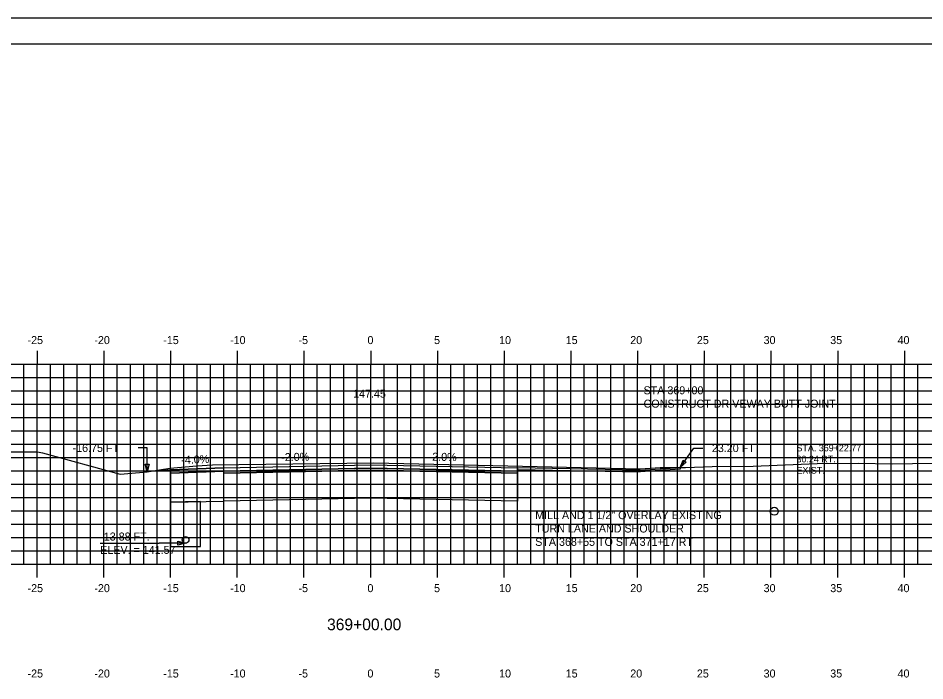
# Model space of a CAD drawing. Extents: x 1147855 to 1148025, y 608981 to 609091.
# Drawn here: x 1147911.8 to 1147979.7, y 609041.6 to 609091.3 of the extents above; entities that cross this region are included whole.
import ezdxf

# ---------------------------------------------------------------- set-up
doc = ezdxf.new("R2010")
doc.units = 0
for name, color, linetype in [('ANNOTATION', 7, 'Continuous'), ('BORDER', 7, 'Continuous'), ('D_Drainage_Underdrain', 7, 'Continuous'), ('D_Drainage_Underdrain_06in', 7, 'Continuous'), ('D_Roadway_Centerline', 7, 'Continuous'), ('D_Roadway_Centerline_Text', 7, 'Continuous'), ('D_Roadway_Drive_Paved', 7, 'Continuous'), ('D_Roadway_Edge_Shoulder', 7, 'Continuous'), ('D_Roadway_Edge_TW', 7, 'Continuous'), ('D_Roadway_Pavement', 7, 'Continuous'), ('D_Roadway_SlopeLines', 7, 'Continuous'), ('D_Roadway_SubGrade', 7, 'Continuous'), ('D_Text_Monospaced', 7, 'Continuous'), ('D_Text_Standard', 7, 'Continuous'), ('H_V ANNOTATION', 7, 'Continuous'), ('MAJOR', 7, 'Continuous'), ('MINOR', 7, 'Continuous'), ('PLOT BOUNDARY', 7, 'Continuous'), ('S_Drainage_Invert', 7, 'Continuous'), ('S_Roadway_Centerline', 7, 'Continuous')]:
    doc.layers.add(name, color=color, linetype=linetype)

msp = doc.modelspace()

# ---------------------------------------------------------------- linework, layer by layer
msp.add_lwpolyline([(1147923.21, 609057.406), (1147923.211, 609057.406), (1147927.211, 609057.566), (1147938.211, 609057.786), (1147949.211, 609057.566)])
at = {"layer": 'BORDER'}
msp.add_lwpolyline([(1147863.211, 608984.335), (1148023.211, 608984.335), (1148023.211, 609089.335), (1147863.211, 609089.335)], close=True, dxfattribs=at)
at = {"layer": 'D_Drainage_Underdrain'}
msp.add_lwpolyline([(1147923.211, 609054.986), (1147923.211, 609051.656), (1147925.461, 609051.656), (1147925.461, 609055.031)], close=True, dxfattribs=at)
at = {"layer": 'D_Drainage_Underdrain_06in'}
msp.add_lwpolyline([(1147924.336, 609052.406), (1147924.413, 609052.394), (1147924.482, 609052.359), (1147924.538, 609052.303), (1147924.573, 609052.234), (1147924.586, 609052.156), (1147924.573, 609052.079), (1147924.538, 609052.009), (1147924.482, 609051.954), (1147924.413, 609051.918), (1147924.336, 609051.906), (1147924.258, 609051.918), (1147924.189, 609051.954), (1147924.133, 609052.009), (1147924.098, 609052.079), (1147924.086, 609052.156), (1147924.098, 609052.234), (1147924.133, 609052.303), (1147924.189, 609052.359), (1147924.258, 609052.394)], close=True, dxfattribs=at)
at = {"layer": 'D_Roadway_Drive_Paved'}
msp.add_line((1147958.411, 609057.382), (1147961.411, 609057.573), dxfattribs=at)
msp.add_lwpolyline([(1147961.411, 609057.573), (1147961.411, 609057.448), (1147958.411, 609057.257)], dxfattribs=at)
at = {"layer": 'D_Roadway_Edge_Shoulder'}
msp.add_line((1147949.211, 609057.441), (1147958.411, 609057.257), dxfattribs=at)
msp.add_lwpolyline([(1147927.211, 609057.566), (1147923.211, 609057.406), (1147923.211, 609057.156), (1147927.211, 609057.316)], close=True, dxfattribs=at)
msp.add_lwpolyline([(1147958.411, 609057.257), (1147958.411, 609057.382), (1147949.211, 609057.566)], dxfattribs=at)
at = {"layer": 'D_Roadway_Edge_TW'}
msp.add_lwpolyline([(1147927.211, 609057.316), (1147927.211, 609057.566), (1147938.211, 609057.786), (1147949.211, 609057.566), (1147949.211, 609057.316), (1147938.211, 609057.536)], close=True, dxfattribs=at)
at = {"layer": 'D_Roadway_Pavement'}
msp.add_lwpolyline([(1147927.211, 609057.15), (1147927.211, 609057.316), (1147938.211, 609057.536), (1147949.211, 609057.316), (1147949.211, 609057.15), (1147938.211, 609057.37)], close=True, dxfattribs=at)
at = {"layer": 'D_Roadway_SlopeLines'}
msp.add_line((1147923.211, 609057.406), (1147921.464, 609057.25), dxfattribs=at)
at = {"layer": 'D_Roadway_SubGrade'}
for points in [[(1147923.21, 609054.986), (1147927.211, 609055.066), (1147927.211, 609057.15), (1147927.211, 609057.316), (1147923.211, 609057.156), (1147923.211, 609057.406), (1147923.21, 609057.406)], [(1147927.211, 609055.066), (1147927.211, 609057.15), (1147938.211, 609057.37), (1147949.211, 609057.15), (1147949.211, 609055.066), (1147938.211, 609055.286)]]:
    msp.add_lwpolyline(points, close=True, dxfattribs=at)
at = {"layer": 'D_Text_Standard'}
msp.add_line((1147917.943, 609051.906), (1147922.357, 609051.906), dxfattribs=at)
for points in [[(1147921.464, 609057.25), (1147921.473, 609059.045), (1147920.793, 609059.045)], [(1147961.411, 609057.573), (1147962.422, 609059.039), (1147963.102, 609059.039)], [(1147924.336, 609051.906), (1147923.037, 609051.906), (1147922.357, 609051.906)]]:
    msp.add_lwpolyline(points, dxfattribs=at)
for points in [[(1147921.464, 609057.25), (1147921.321, 609057.832), (1147921.612, 609057.831)], [(1147961.411, 609057.573), (1147961.621, 609058.135), (1147961.861, 609057.97)], [(1147924.336, 609051.906), (1147923.753, 609051.761), (1147923.753, 609052.052)]]:
    msp.add_lwpolyline(points, close=True, dxfattribs=at)
at = {"layer": 'MAJOR'}
for p, q in [((1147913.211, 609066.337), (1147913.211, 609065.335)), ((1147918.211, 609066.337), (1147918.211, 609065.335)), ((1147923.211, 609066.337), (1147923.211, 609065.335)), ((1147928.211, 609066.337), (1147928.211, 609065.335)), ((1147933.211, 609066.337), (1147933.211, 609065.335)), ((1147938.211, 609066.337), (1147938.211, 609065.335)), ((1147943.211, 609066.337), (1147943.211, 609065.335)), ((1147948.211, 609066.337), (1147948.211, 609065.335)), ((1147953.211, 609066.337), (1147953.211, 609065.335)), ((1147958.211, 609066.337), (1147958.211, 609065.335)), ((1147963.211, 609066.337), (1147963.211, 609065.335)), ((1147968.211, 609066.337), (1147968.211, 609065.335)), ((1147973.211, 609066.337), (1147973.211, 609065.335)), ((1147978.211, 609066.337), (1147978.211, 609065.335)), ((1147868.211, 609065.335), (1148008.211, 609065.335)), ((1147868.211, 609065.335), (1148008.211, 609065.335)), ((1147913.211, 609050.335), (1147913.211, 609065.335)), ((1147918.211, 609050.335), (1147918.211, 609065.335)), ((1147923.211, 609050.335), (1147923.211, 609065.335)), ((1147928.211, 609050.335), (1147928.211, 609065.335)), ((1147933.211, 609050.335), (1147933.211, 609065.335)), ((1147938.211, 609050.335), (1147938.211, 609065.335)), ((1147943.211, 609050.335), (1147943.211, 609065.335)), ((1147948.211, 609050.335), (1147948.211, 609065.335)), ((1147953.211, 609050.335), (1147953.211, 609065.335)), ((1147958.211, 609050.335), (1147958.211, 609065.335)), ((1147963.211, 609050.335), (1147963.211, 609065.335)), ((1147968.211, 609050.335), (1147968.211, 609065.335)), ((1147973.211, 609050.335), (1147973.211, 609065.335)), ((1147978.211, 609050.335), (1147978.211, 609065.335)), ((1147868.211, 609060.335), (1148008.211, 609060.335)), ((1147868.211, 609055.335), (1148008.211, 609055.335)), ((1147868.211, 609050.335), (1148008.211, 609050.335)), ((1147868.211, 609050.335), (1148008.211, 609050.335)), ((1147913.211, 609049.333), (1147913.211, 609050.335)), ((1147918.211, 609049.333), (1147918.211, 609050.335)), ((1147923.211, 609049.333), (1147923.211, 609050.335)), ((1147928.211, 609049.333), (1147928.211, 609050.335)), ((1147933.211, 609049.333), (1147933.211, 609050.335)), ((1147938.211, 609049.333), (1147938.211, 609050.335)), ((1147943.211, 609049.333), (1147943.211, 609050.335)), ((1147948.211, 609049.333), (1147948.211, 609050.335)), ((1147953.211, 609049.333), (1147953.211, 609050.335)), ((1147958.211, 609049.333), (1147958.211, 609050.335)), ((1147963.211, 609049.333), (1147963.211, 609050.335)), ((1147968.211, 609049.333), (1147968.211, 609050.335)), ((1147973.211, 609049.333), (1147973.211, 609050.335)), ((1147978.211, 609049.333), (1147978.211, 609050.335))]:
    msp.add_line(p, q, dxfattribs=at)
at = {"layer": 'MINOR'}
for p, q in [((1147912.211, 609050.335), (1147912.211, 609065.335)), ((1147914.211, 609050.335), (1147914.211, 609065.335)), ((1147915.211, 609050.335), (1147915.211, 609065.335)), ((1147916.211, 609050.335), (1147916.211, 609065.335)), ((1147917.211, 609050.335), (1147917.211, 609065.335)), ((1147919.211, 609050.335), (1147919.211, 609065.335)), ((1147920.211, 609050.335), (1147920.211, 609065.335)), ((1147921.211, 609050.335), (1147921.211, 609065.335)), ((1147922.211, 609050.335), (1147922.211, 609065.335)), ((1147924.211, 609050.335), (1147924.211, 609065.335)), ((1147925.211, 609050.335), (1147925.211, 609065.335)), ((1147926.211, 609050.335), (1147926.211, 609065.335)), ((1147927.211, 609050.335), (1147927.211, 609065.335)), ((1147929.211, 609050.335), (1147929.211, 609065.335)), ((1147930.211, 609050.335), (1147930.211, 609065.335)), ((1147931.211, 609050.335), (1147931.211, 609065.335)), ((1147932.211, 609050.335), (1147932.211, 609065.335)), ((1147934.211, 609050.335), (1147934.211, 609065.335)), ((1147935.211, 609050.335), (1147935.211, 609065.335)), ((1147936.211, 609050.335), (1147936.211, 609065.335)), ((1147937.211, 609050.335), (1147937.211, 609065.335)), ((1147939.211, 609050.335), (1147939.211, 609065.335)), ((1147940.211, 609050.335), (1147940.211, 609065.335)), ((1147941.211, 609050.335), (1147941.211, 609065.335)), ((1147942.211, 609050.335), (1147942.211, 609065.335)), ((1147944.211, 609050.335), (1147944.211, 609065.335)), ((1147945.211, 609050.335), (1147945.211, 609065.335)), ((1147946.211, 609050.335), (1147946.211, 609065.335)), ((1147947.211, 609050.335), (1147947.211, 609065.335)), ((1147949.211, 609050.335), (1147949.211, 609065.335)), ((1147950.211, 609050.335), (1147950.211, 609065.335)), ((1147951.211, 609050.335), (1147951.211, 609065.335)), ((1147952.211, 609050.335), (1147952.211, 609065.335)), ((1147954.211, 609050.335), (1147954.211, 609065.335)), ((1147955.211, 609050.335), (1147955.211, 609065.335)), ((1147956.211, 609050.335), (1147956.211, 609065.335)), ((1147957.211, 609050.335), (1147957.211, 609065.335)), ((1147959.211, 609050.335), (1147959.211, 609065.335)), ((1147960.211, 609050.335), (1147960.211, 609065.335)), ((1147961.211, 609050.335), (1147961.211, 609065.335)), ((1147962.211, 609050.335), (1147962.211, 609065.335)), ((1147964.211, 609050.335), (1147964.211, 609065.335)), ((1147965.211, 609050.335), (1147965.211, 609065.335)), ((1147966.211, 609050.335), (1147966.211, 609065.335)), ((1147967.211, 609050.335), (1147967.211, 609065.335)), ((1147969.211, 609050.335), (1147969.211, 609065.335)), ((1147970.211, 609050.335), (1147970.211, 609065.335)), ((1147971.211, 609050.335), (1147971.211, 609065.335)), ((1147972.211, 609050.335), (1147972.211, 609065.335)), ((1147974.211, 609050.335), (1147974.211, 609065.335)), ((1147975.211, 609050.335), (1147975.211, 609065.335)), ((1147976.211, 609050.335), (1147976.211, 609065.335)), ((1147977.211, 609050.335), (1147977.211, 609065.335)), ((1147979.211, 609050.335), (1147979.211, 609065.335)), ((1147868.211, 609064.335), (1148008.211, 609064.335)), ((1147868.211, 609063.335), (1148008.211, 609063.335)), ((1147868.211, 609062.335), (1148008.211, 609062.335)), ((1147868.211, 609061.335), (1148008.211, 609061.335)), ((1147868.211, 609059.335), (1148008.211, 609059.335)), ((1147868.211, 609058.335), (1148008.211, 609058.335)), ((1147868.211, 609057.335), (1148008.211, 609057.335)), ((1147868.211, 609056.335), (1148008.211, 609056.335)), ((1147868.211, 609054.335), (1148008.211, 609054.335)), ((1147868.211, 609053.335), (1148008.211, 609053.335)), ((1147868.211, 609052.335), (1148008.211, 609052.335)), ((1147868.211, 609051.335), (1148008.211, 609051.335))]:
    msp.add_line(p, q, dxfattribs=at)
at = {"layer": 'PLOT BOUNDARY'}
msp.add_lwpolyline([(1147855.117, 608981.276), (1148025.117, 608981.276), (1148025.117, 609091.276), (1147855.117, 609091.276)], close=True, dxfattribs=at)
at = {"layer": 'S_Drainage_Invert'}
msp.add_circle((1147968.455, 609054.298), 0.3, dxfattribs=at)
at = {"layer": 'S_Roadway_Centerline'}
msp.add_lwpolyline([(1147876.627, 609059.215), (1147887.18, 609058.993), (1147889.241, 609058.903), (1147892.857, 609058.818), (1147909.277, 609058.762), (1147913.241, 609058.762), (1147913.605, 609058.678), (1147919.446, 609057.084), (1147921.464, 609057.25), (1147923.171, 609057.543), (1147925.188, 609057.705), (1147926.357, 609057.777), (1147928.34, 609057.797), (1147938.457, 609057.934), (1147944.059, 609057.8), (1147958.404, 609057.477), (1147959.911, 609057.57), (1147961.807, 609057.574), (1147963.81, 609057.667), (1147966.876, 609057.692), (1147971.682, 609057.89), (1147974.776, 609057.896), (1147977.299, 609057.854), (1147987.896, 609058.024)], dxfattribs=at)

# ---------------------------------------------------------------- texts
at = {"layer": 'ANNOTATION'}
for s, p in [('STA 369+00', (1147958.663, 609063.071)), ('CONSTRUCT DRIVEWAY BUTT JOINT', (1147958.663, 609062.069)), ('MILL AND 1 1/2" OVERLAY EXISTING', (1147950.541, 609053.71)), ('TURN LANE AND SHOULDER', (1147950.541, 609052.708)), ('STA 368+55 TO STA 371+17 RT', (1147950.541, 609051.706))]:
    msp.add_text(s, height=0.6, dxfattribs=at).set_placement(p)
for s, rotation, p in [('-4.0%', 2.29061, (1147924.026, 609057.84)), ('-2.0%', 1.14576, (1147931.514, 609058.053)), ('-2.0%', 358.85424, (1147942.554, 609058.1))]:
    msp.add_text(s, height=0.6, rotation=rotation, dxfattribs=at).set_placement(p)
at = {"layer": 'D_Roadway_Centerline'}
for s, p in [('C', (1147938.205, 609057.786)), ('L', (1147938.211, 609057.779))]:
    msp.add_text(s, height=0.0146, dxfattribs=at).set_placement(p)
at = {"layer": 'D_Roadway_Centerline_Text'}
msp.add_text('147.45', height=0.6, dxfattribs=at).set_placement((1147936.892, 609062.818))
at = {"layer": 'D_Text_Monospaced'}
for s, height, p in [('STA. 369+22.77', 0.49998, (1147970.122, 609058.796)), ('30.24 RT.', 0.5, (1147970.122, 609057.962)), ('EXIST. ', 0.5, (1147970.122, 609057.122))]:
    msp.add_text(s, height=height, dxfattribs=at).set_placement(p)
at = {"layer": 'D_Text_Standard'}
for s, p in [('-16.75 FT', (1147915.873, 609058.745)), ('23.20 FT', (1147963.782, 609058.739)), ('-13.88 FT.', (1147917.943, 609052.106)), ('ELEV. = 141.57', (1147917.943, 609051.106))]:
    msp.add_text(s, height=0.6, dxfattribs=at).set_placement(p)
at = {"layer": 'H_V ANNOTATION'}
for s, height, p in [('-25', 0.6, (1147912.496, 609066.835)), ('-20', 0.6, (1147917.504, 609066.835)), ('-15', 0.6, (1147922.667, 609066.835)), ('-10', 0.6, (1147927.675, 609066.835)), ('-5', 0.6, (1147932.801, 609066.835)), ('0', 0.6, (1147937.97, 609066.835)), ('5', 0.6, (1147942.962, 609066.835)), ('10', 0.6, (1147947.836, 609066.835)), ('15', 0.6, (1147952.828, 609066.835)), ('20', 0.6, (1147957.665, 609066.835)), ('25', 0.6, (1147962.657, 609066.835)), ('30', 0.6, (1147967.659, 609066.835)), ('35', 0.6, (1147972.651, 609066.835)), ('40', 0.6, (1147977.697, 609066.835)), ('-25', 0.6, (1147912.496, 609048.235)), ('-20', 0.6, (1147917.504, 609048.235)), ('-15', 0.6, (1147922.667, 609048.235)), ('-10', 0.6, (1147927.675, 609048.235)), ('-5', 0.6, (1147932.801, 609048.235)), ('0', 0.6, (1147937.97, 609048.235)), ('5', 0.6, (1147942.962, 609048.235)), ('10', 0.6, (1147947.836, 609048.235)), ('15', 0.6, (1147952.828, 609048.235)), ('20', 0.6, (1147957.665, 609048.235)), ('25', 0.6, (1147962.657, 609048.235)), ('30', 0.6, (1147967.659, 609048.235)), ('35', 0.6, (1147972.651, 609048.235)), ('40', 0.6, (1147977.697, 609048.235)), ('369+00.00', 0.875, (1147934.941, 609045.378)), ('-25', 0.6, (1147912.496, 609041.835)), ('-20', 0.6, (1147917.504, 609041.835)), ('-15', 0.6, (1147922.667, 609041.835)), ('-10', 0.6, (1147927.675, 609041.835)), ('-5', 0.6, (1147932.801, 609041.835)), ('0', 0.6, (1147937.97, 609041.835)), ('5', 0.6, (1147942.962, 609041.835)), ('10', 0.6, (1147947.836, 609041.835)), ('15', 0.6, (1147952.828, 609041.835)), ('20', 0.6, (1147957.665, 609041.835)), ('25', 0.6, (1147962.657, 609041.835)), ('30', 0.6, (1147967.659, 609041.835)), ('35', 0.6, (1147972.651, 609041.835)), ('40', 0.6, (1147977.697, 609041.835))]:
    msp.add_text(s, height=height, dxfattribs=at).set_placement(p)
at = {"layer": 'S_Roadway_Centerline'}
for s, p in [('C', (1147938.452, 609057.934)), ('L', (1147938.457, 609057.927))]:
    msp.add_text(s, height=0.0146, dxfattribs=at).set_placement(p)

doc.saveas('drawing.dxf')
